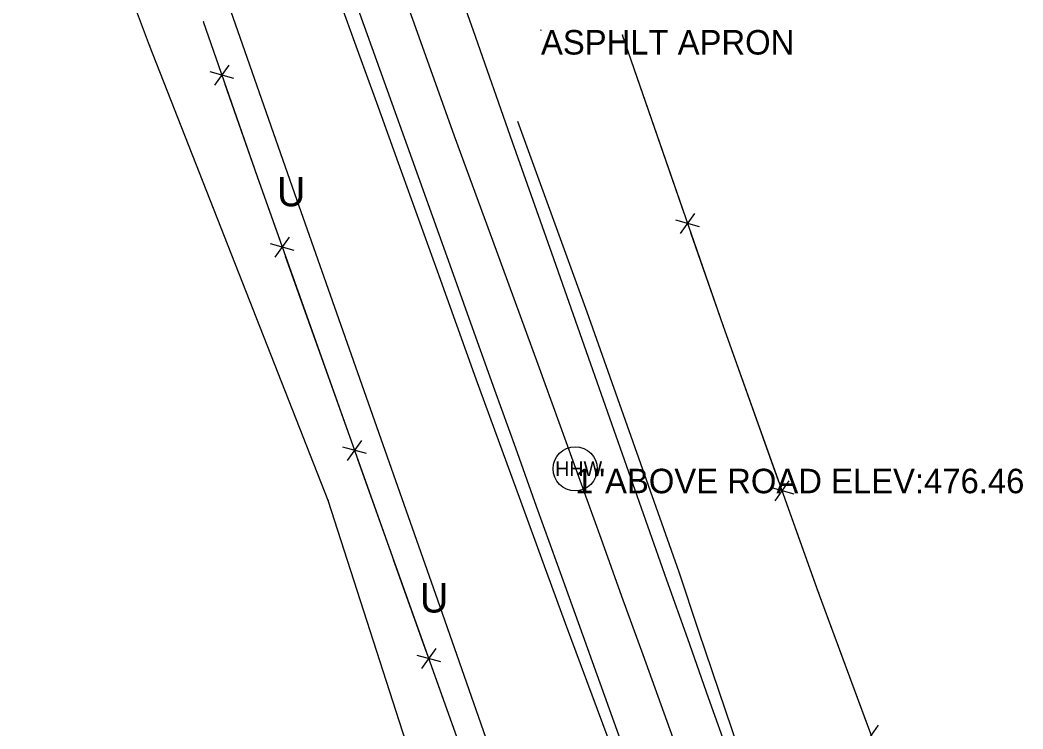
# Model space of a CAD drawing. Extents: x 1050807 to 1053552, y 395828 to 398415.
# Drawn here: x 1052217.7 to 1052422.1, y 397054.1 to 397198.7 of the extents above; entities that cross this region are included whole.
import ezdxf

# ---------------------------------------------------------------- set-up
doc = ezdxf.new("R2010")
doc.units = 0
for name, color, linetype in [('Default', 7, 'Continuous'), ('S_EDGE_PAVEMENT', 7, 'Continuous'), ('S_FENCE', 7, 'Continuous'), ('S_HIST_HIGH_WATER', 7, 'Continuous'), ('S_HIST_HIGH_WATER_ANNOT', 7, 'Continuous'), ('S_MSC_PT_SYM', 7, 'Continuous'), ('S_PAVEMENT_CROWN', 7, 'Continuous'), ('S_SHOULDER', 7, 'Continuous'), ('S_SURVEY_TEXT_ANNOT', 7, 'Continuous'), ('S_UNDERGROUND_CABLE', 7, 'Continuous'), ('S_UTL_PT_SYM', 7, 'Continuous'), ('S_WATER_UTILITIES', 7, 'Continuous')]:
    doc.layers.add(name, color=color, linetype=linetype)

msp = doc.modelspace()

# ---------------------------------------------------------------- linework, layer by layer
at = {"layer": 'S_EDGE_PAVEMENT'}
for points in [[(1052366.56, 397036.55), (1052362.3, 397048.53), (1052358.05, 397060.51), (1052353.79, 397072.49), (1052349.54, 397084.47), (1052341.79, 397106.52), (1052334.05, 397128.57), (1052326.07, 397151.2), (1052318.09, 397173.83), (1052310.11, 397196.56), (1052302.13, 397219.28), (1052294.23, 397241.56), (1052286.33, 397263.84), (1052278.39, 397285.89), (1052270.44, 397307.95), (1052265.77, 397320.81), (1052261.1, 397333.67), (1052256.44, 397346.52), (1052251.77, 397359.38), (1052244.05, 397379.98), (1052236.34, 397400.57)], [(1052358.04, 397002.59), (1052353.03, 397016.23), (1052348.02, 397029.87), (1052339.76, 397052.84), (1052331.5, 397075.82), (1052327.24, 397087.68), (1052322.99, 397099.53), (1052318.74, 397111.39), (1052314.49, 397123.25), (1052310.27, 397135.03), (1052306.04, 397146.82), (1052301.81, 397158.61), (1052297.59, 397170.39), (1052289.45, 397193.11), (1052281.31, 397215.83), (1052273.5, 397237.65), (1052265.69, 397259.46), (1052257.46, 397282.59), (1052249.24, 397305.71), (1052241.37, 397327.67), (1052233.5, 397349.63), (1052225.59, 397371.79), (1052217.68, 397393.96)]]:
    msp.add_lwpolyline(points, dxfattribs=at)
at = {"layer": 'S_FENCE'}
for p, q in [((1052266.07, 397166.74), (1052255.07, 397198.36)), ((1052360.99, 397136.45), (1052340.48, 397195.66)), ((1052261.25, 397186.83), (1052256.44, 397188.2)), ((1052261.25, 397186.83), (1052256.44, 397188.2)), ((1052257.38, 397185.49), (1052260.31, 397189.54)), ((1052257.38, 397185.49), (1052260.31, 397189.54)), ((1052293.27, 397090.24), (1052266.07, 397166.74)), ((1052352.32, 397155.21), (1052355.25, 397159.26)), ((1052352.32, 397155.21), (1052355.25, 397159.26)), ((1052356.19, 397156.55), (1052351.38, 397157.92)), ((1052356.19, 397156.55), (1052351.38, 397157.92)), ((1052273.57, 397151.76), (1052268.75, 397153.09)), ((1052273.57, 397151.76), (1052268.75, 397153.09)), ((1052269.71, 397150.39), (1052272.61, 397154.46)), ((1052269.71, 397150.39), (1052272.61, 397154.46)), ((1052380.46, 397081.99), (1052360.99, 397136.45)), ((1052284.45, 397108.93), (1052287.35, 397113)), ((1052284.45, 397108.93), (1052287.35, 397113)), ((1052288.31, 397110.3), (1052283.49, 397111.63)), ((1052288.31, 397110.3), (1052283.49, 397111.63)), ((1052371.61, 397100.66), (1052374.5, 397104.74)), ((1052371.61, 397100.66), (1052374.5, 397104.74)), ((1052375.47, 397102.04), (1052370.64, 397103.36)), ((1052375.47, 397102.04), (1052370.64, 397103.36)), ((1052323.23, 397006.32), (1052293.27, 397090.24)), ((1052398.87, 397032.26), (1052380.46, 397081.99)), ((1052303.45, 397067.82), (1052298.63, 397069.14)), ((1052303.45, 397067.82), (1052298.63, 397069.14)), ((1052299.59, 397066.44), (1052302.49, 397070.52)), ((1052299.59, 397066.44), (1052302.49, 397070.52)), ((1052389.81, 397050.83), (1052392.66, 397054.94)), ((1052389.81, 397050.83), (1052392.66, 397054.94))]:
    msp.add_line(p, q, dxfattribs=at)
for points in [[(1052258.19, 397189.4), (1052255.07, 397198.36)], [(1052258.19, 397189.4), (1052255.07, 397198.36)], [(1052353.13, 397159.13), (1052340.48, 397195.66)], [(1052353.13, 397159.13), (1052340.48, 397195.66)], [(1052266.07, 397166.74), (1052259.5, 397185.62)], [(1052266.07, 397166.74), (1052259.5, 397185.62)], [(1052270.68, 397153.77), (1052266.07, 397166.74)], [(1052270.68, 397153.77), (1052266.07, 397166.74)], [(1052360.99, 397136.45), (1052354.44, 397155.35)], [(1052360.99, 397136.45), (1052354.44, 397155.35)], [(1052285.23, 397112.85), (1052271.83, 397150.54)], [(1052285.23, 397112.85), (1052271.83, 397150.54)], [(1052372.38, 397104.58), (1052360.99, 397136.45)], [(1052372.38, 397104.58), (1052360.99, 397136.45)], [(1052293.27, 397090.24), (1052286.57, 397109.08)], [(1052293.27, 397090.24), (1052286.57, 397109.08)], [(1052380.46, 397081.99), (1052373.73, 397100.82)], [(1052380.46, 397081.99), (1052373.73, 397100.82)], [(1052300.56, 397069.83), (1052293.83, 397088.67)], [(1052300.56, 397069.83), (1052293.83, 397088.67)], [(1052390.54, 397054.76), (1052380.46, 397081.99)], [(1052390.54, 397054.76), (1052380.46, 397081.99)], [(1052315.16, 397028.93), (1052301.71, 397066.6)], [(1052315.16, 397028.93), (1052301.71, 397066.6)]]:
    msp.add_lwpolyline(points, dxfattribs=at)
at = {"layer": 'S_HIST_HIGH_WATER'}
msp.add_circle((1052330.85, 397107.22), 4.5, dxfattribs=at)
at = {"layer": 'S_MSC_PT_SYM'}
for points in [[(1052255.07, 397198.36), (1052255.07, 397198.41), (1052255.07, 397198.36), (1052255.02, 397198.36), (1052255.07, 397198.36), (1052255.07, 397198.31), (1052255.07, 397198.36), (1052255.12, 397198.36)], [(1052323.88, 397196.71), (1052323.88, 397196.76), (1052323.88, 397196.71), (1052323.83, 397196.71), (1052323.88, 397196.71), (1052323.88, 397196.66), (1052323.88, 397196.71), (1052323.93, 397196.71)], [(1052340.48, 397195.66), (1052340.48, 397195.71), (1052340.48, 397195.66), (1052340.43, 397195.66), (1052340.48, 397195.66), (1052340.48, 397195.61), (1052340.48, 397195.66), (1052340.53, 397195.66)], [(1052266.07, 397166.74), (1052266.07, 397166.79), (1052266.07, 397166.74), (1052266.02, 397166.74), (1052266.07, 397166.74), (1052266.07, 397166.69), (1052266.07, 397166.74), (1052266.12, 397166.74)], [(1052360.99, 397136.45), (1052360.99, 397136.5), (1052360.99, 397136.45), (1052360.94, 397136.45), (1052360.99, 397136.45), (1052360.99, 397136.4), (1052360.99, 397136.45), (1052361.04, 397136.45)], [(1052293.27, 397090.24), (1052293.27, 397090.29), (1052293.27, 397090.24), (1052293.22, 397090.24), (1052293.27, 397090.24), (1052293.27, 397090.19), (1052293.27, 397090.24), (1052293.32, 397090.24)], [(1052380.46, 397081.99), (1052380.46, 397082.04), (1052380.46, 397081.99), (1052380.41, 397081.99), (1052380.46, 397081.99), (1052380.46, 397081.94), (1052380.46, 397081.99), (1052380.51, 397081.99)]]:
    msp.add_lwpolyline(points, dxfattribs=at)
at = {"layer": 'S_PAVEMENT_CROWN'}
msp.add_lwpolyline([(1052366.34, 397010.04), (1052362.68, 397019.85), (1052357.54, 397033.59), (1052353.25, 397045.49), (1052348.97, 397057.39), (1052344.68, 397069.29), (1052340.39, 397081.19), (1052336.12, 397093.01), (1052331.85, 397104.83), (1052327.58, 397116.64), (1052323.31, 397128.46), (1052314.8, 397151.75), (1052306.28, 397175.04), (1052298.35, 397197.17), (1052290.41, 397219.3)], dxfattribs=at)
at = {"layer": 'S_SHOULDER'}
for points in [[(1052355.65, 397004.17), (1052350.97, 397016.49), (1052346.3, 397028.81), (1052337.6, 397052.24), (1052328.9, 397075.66), (1052324.34, 397088.12), (1052319.79, 397100.59), (1052315.23, 397113.05), (1052310.67, 397125.51), (1052302.75, 397147.54), (1052294.83, 397169.57), (1052290.39, 397181.87), (1052285.96, 397194.16), (1052281.52, 397206.46), (1052277.09, 397218.75)], [(1052376.91, 397011.59), (1052372.6, 397024.74), (1052368.29, 397037.89), (1052364.22, 397049.94), (1052360.16, 397061.99), (1052356.09, 397074.04), (1052352.02, 397086.1), (1052347.33, 397099.36), (1052342.65, 397112.63), (1052337.97, 397125.9), (1052333.29, 397139.16), (1052326.21, 397158.59), (1052319.13, 397178.02)]]:
    msp.add_lwpolyline(points, dxfattribs=at)
at = {"layer": 'S_UNDERGROUND_CABLE'}
for p, q in [((1052273.7, 397163.31), (1052241.5, 397255.38)), ((1052302.83, 397080.43), (1052273.7, 397163.31)), ((1052329.44, 397004.35), (1052302.83, 397080.43))]:
    msp.add_line(p, q, dxfattribs=at)
at = {"layer": 'S_UTL_PT_SYM'}
for points in [[(1052244.07, 397193.55), (1052244.07, 397193.6), (1052244.07, 397193.55), (1052244.02, 397193.55), (1052244.07, 397193.55), (1052244.07, 397193.5), (1052244.07, 397193.55), (1052244.12, 397193.55)], [(1052280.47, 397100.74), (1052280.47, 397100.79), (1052280.47, 397100.74), (1052280.42, 397100.74), (1052280.47, 397100.74), (1052280.47, 397100.69), (1052280.47, 397100.74), (1052280.52, 397100.74)]]:
    msp.add_lwpolyline(points, dxfattribs=at)
at = {"layer": 'S_WATER_UTILITIES'}
for p, q in [((1052244.07, 397193.55), (1052223.15, 397249.48)), ((1052280.47, 397100.74), (1052244.07, 397193.55)), ((1052308.23, 397014.61), (1052280.47, 397100.74))]:
    msp.add_line(p, q, dxfattribs=at)

# ---------------------------------------------------------------- texts
at = {"layer": 'Default'}
for p in [(1052270.07, 397160.76), (1052299.21, 397077.89)]:
    msp.add_text('U', height=6, dxfattribs=at).set_placement(p)
at = {"layer": 'S_HIST_HIGH_WATER'}
msp.add_text('HHW', height=3, dxfattribs=at).set_placement((1052326.77, 397105.72))
at = {"layer": 'S_HIST_HIGH_WATER_ANNOT'}
msp.add_text('1"ABOVE ROAD ELEV:476.46', height=5, dxfattribs=at).set_placement((1052330.85, 397102.22))
at = {"layer": 'S_SURVEY_TEXT_ANNOT'}
msp.add_text('ASPHLT APRON', height=5, dxfattribs=at).set_placement((1052323.88, 397191.71))

doc.saveas('drawing.dxf')
